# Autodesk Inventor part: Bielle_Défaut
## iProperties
Shininess: 64.0
Length Units: 11269
Angle Units: 11279
Time Units: 11290
Mass Units: 11283
Length Display Precision: 3
Angle Display Precision: 2
Compacted: True
Part Number: Bielle_Défaut
Document SubType Name: Modeling
Created: 2006-01
Material: Par défaut
Designer: riri
Density: 0.0
Volumn: 0.0
Area: 0.0
PropertySet Name: Model Information
Control State: 0
Master: False
Checked Out: False
Author: riri
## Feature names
1. Base1
